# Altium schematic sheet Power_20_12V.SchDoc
size A4
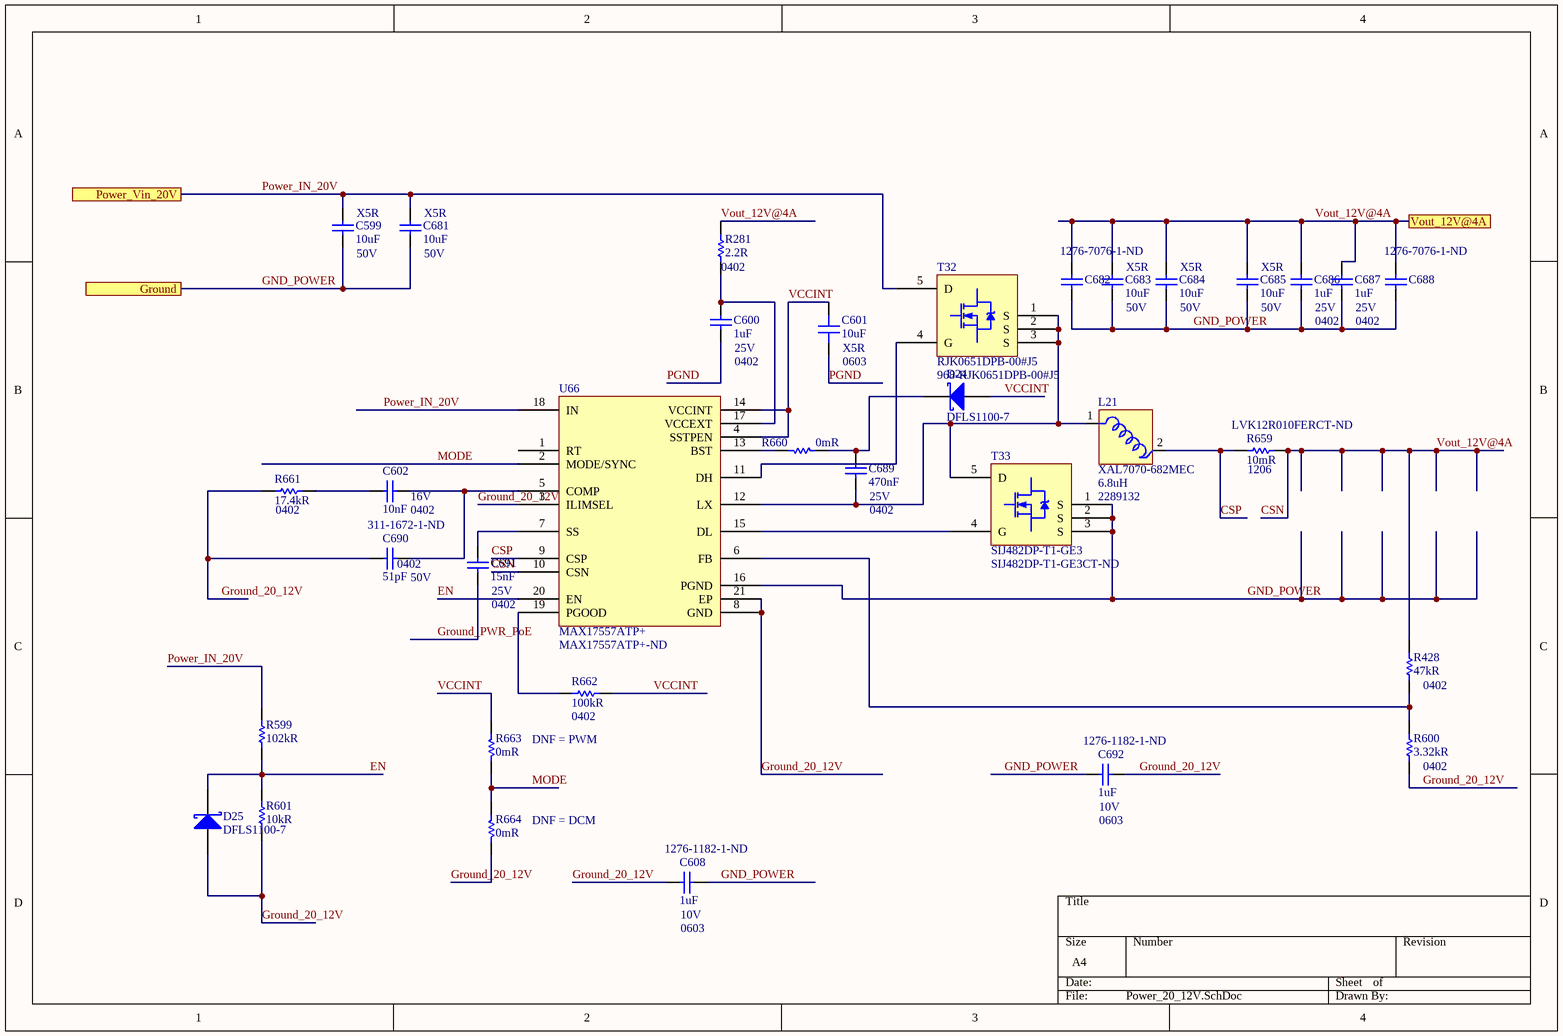
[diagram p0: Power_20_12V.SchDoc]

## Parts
C599  10uF  Voltage Rating (DC): 50V  Dielectric: X5R  [CAP 0805/2012 RF]
C600  1uF  Case/Package: 0402  Voltage Rating: 25V  [CAP 0402/1005 RF]
C601  10uF  Case/Package: 0603  Dielectric: X5R  [CAP 0603/1608 RF]
C602  10nF  Case/Package: 0402  Voltage Rating: 16V  [CAP 0402/1005 RF]
C608  1uF  Supplier Part Number 1: 1276-1182-1-ND  Case/Package: 0603  Voltage Rating: 10V  [CAP 0603/1608 RF]
C681  10uF  Voltage Rating (DC): 50V  Dielectric: X5R  [CAP 0805/2012 RF]
C682  Supplier Part Number 1: 1276-7076-1-ND  [CAP 0603/1608 RF]  (hidden comment: 22uF)
C683  10uF  Voltage Rating (DC): 50V  Dielectric: X5R  [CAP 0805/2012 RF]
C684  10uF  Voltage Rating (DC): 50V  Dielectric: X5R  [CAP 0805/2012 RF]
C685  10uF  Voltage Rating (DC): 50V  Dielectric: X5R  [CAP 0805/2012 RF]
C686  1uF  Case/Package: 0402  Voltage Rating: 25V  [CAP 0402/1005 RF]
C687  1uF  Case/Package: 0402  Voltage Rating: 25V  [CAP 0402/1005 RF]
C688  Supplier Part Number 1: 1276-7076-1-ND  [CAP 0603/1608 RF]  (hidden comment: 22uF)
C689  470nF  Case/Package: 0402  Voltage Rating: 25V  [CAP 0402/1005 RF]
C690  51pF  Supplier Part Number 1: 311-1672-1-ND  Case/Package: 0402  Voltage Rating: 50V  [CAP 0402/1005 RF]
C691  15nF  Case/Package: 0402  Voltage Rating: 25V  [CAP 0402/1005 RF]
C692  1uF  Supplier Part Number 1: 1276-1182-1-ND  Case/Package: 0603  Voltage Rating: 10V  [CAP 0603/1608 RF]
D24  DFLS1100-7  [DFLS1100]
D25  DFLS1100-7  [DFLS1100]
L21  XAL7070-682MEC  Inductance: 6.8uH  Supplier Part Number 1: 2289132
R281  2.2R  Case Code (Imperial): 0402  [RES 0402/1005 RF]
R428  47kR  Case/Package: 0402  [RES 0402/1005 RF]
R599  102kR  [RES 1206/3216]
R600  3.32kR  Case/Package: 0402  [RES 0402/1005 RF]
R601  10kR  [RES 0402/1005 RF]
R659  10mR  Supplier Part Number 1: LVK12R010FERCT-ND  Case/Package: 1206  [RES 1206/3216]
R660  0mR  [RES 0402/1005 RF]
R661  17.4kR  Case/Package: 0402  [RES 0402/1005 RF]
R662  100kR  Case/Package: 0402  [RES 0402/1005 RF]
R663  0mR  [RES 0402/1005 RF]
R664  0mR  [RES 0402/1005 RF]
T32  RJK0651DPB-00#J5  Supplier Part Number 1: 968-RJK0651DPB-00#J5  [RJK0651DPB]
T33  SIJ482DP-T1-GE3  Supplier Part Number 1: SIJ482DP-T1-GE3CT-ND  [SiJ482DP]
U66  MAX17557ATP+  Supplier Part Number 1: MAX17557ATP+-ND  [MAX17557]

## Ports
Ground, Power_Vin_20V, Vout_12V@4A

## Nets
CSN: C682.2 C683.2 C684.2 C685.2 C686.2 C687.2 C688.2 R281.2 R428.2 R659.2 U66.10(CSN) ; port Vout_12V@4A  [also labelled Vout_12V@4A]
CSP: L21.2 R659.1 U66.9(CSP)
EN: D25.1(K) R599.1 R601.1 U66.20(EN)
GND_POWER: C599.1 C608.2 C681.1 C682.1 C683.1 C684.1 C685.1 C686.1 C687.1 C688.1 C692.1 T33.1(S) T33.2(S) T33.3(S) U66.16(PGND) ; port Ground
Ground_20_12V: C608.1 C690.2 C692.2 D25.2(A) R600.1 R601.2 R661.1 R664.2 U66.3(ILIMSEL) U66.8(GND) U66.21(EP)
Ground_PWR_PoE: C691.1
MODE: R663.2 R664.1 U66.2(MODE/SYNC)
PGND: C600.1 C601.1
Power_IN_20V: C599.2 C681.2 R599.2 T32.5(D) U66.18(IN) ; port Power_Vin_20V
VCCINT: C601.2 D24.2(A) R662.1 R663.1 U66.4(SSTPEN) U66.14(VCCINT)
NetC600_2: C600.2 R281.1 U66.17(VCCEXT)
NetC602_1: C602.1 R661.2
NetC602_2: C602.2 C690.1 U66.5(COMP)
NetC689_1: C689.1 L21.1 T32.1(S) T32.2(S) T32.3(S) T33.5(D) U66.12(LX)
NetC689_2: C689.2 D24.1(K) R660.1
NetC691_2: C691.2 U66.7(SS)
NetR428_1: R428.1 R600.2 U66.6(FB)
NetR660_2: R660.2 U66.13(BST)
NetR662_2: R662.2 U66.19(PGOOD)
NetT32_4: T32.4(G) U66.11(DH)
NetT33_4: T33.4(G) U66.15(DL)

Not connected (* = marked no-connect by the designer): U66 1(RT)

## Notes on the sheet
- DNF = PWM
- (near R664) DNF = DCM

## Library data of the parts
C599 C681 C683-C685 = Capacitor: Manufacturer: Murata; Manufacturer Part Number: GRM21BR61H106KE43L; Tolerance: 10%
C600 C686 C687 = Capacitor: MURATA - GRT155R61E105KE01D - SMD Multilayer Ceramic Capacitor, 1 µF, 25 V, 0402 [1005 Metric], ± 10%, X5R, GRT Series - SMD Multilayer Ceramic Capacitor, 1 µF, 25 V, 0402 [1005 Metric], ± 10%, X5R, GRT Series
C601 = Capacitor: Manufacturer: Murata; Manufacturer Part Number: GRM188R61A106KE69D; Tolerance: 10%; Voltage Rating: 10V
C602 = Capacitor: CAP CER 10000PF 16V X7R 0402; Manufacturer: Yageo; Manufacturer Part Number: CC0402KRX7R7BB103; Tolerance: 10%; Insulation Resistance: 10GR; Dissipation Factor: 3.5%
C608 C692 = Capacitor: Cap Ceramic 1uF 10V X5R 10% SMD 0603 85C Paper T/R; Manufacturer: Samsung; Manufacturer Part Number: CL10A105KP8NNNC
C682 C688 = Capacitor: CAP CER 22UF 16V X5R 0603; Manufacturer: Samsung; Manufacturer Part Number: CL10A226MO7JZNC
C689 = Capacitor: CAP CER 0.47UF 25V X5R 0402; Manufacturer: Murata; Manufacturer Part Number: GRT155R61E474KE01D; Tolerance: 10%
C690 = Capacitor: Cap Ceramic 51pF 50V C0G 5% SMD 0402 125C Paper T/R; Manufacturer: Yageo; Manufacturer Part Number: CC0402JRNPO9BN510
C691 = Capacitor: Cap Ceramic 0.015uF 25V X7R 10% SMD 0402 125C Paper T/R; Manufacturer: Yageo; Manufacturer Part Number: CC0402KRX7R8BB153
D24 D25 = DFLS1100-7: DIODE SCHOTTKY 100V POWERDI123; Manufacturer: Diodes; Forward Voltage: 770mV; Forward Current: 1A; Peak Reverse Current: 1uA; Peak Non-Repetitive Surge Current: 50A; Max Forward Surge Current (Ifsm): 40A; Element Configuration: Single; Polarity: Standard; Capacitance: 36pF
L21 = XAL7070-682MEC: Power inductor, shielded, 20% tol, SMT, RoHS, halogen f; Manufacturer: Coilcraft; Core Material: Composite; Max DC Current: 9.2A; Self Resonant Frequency: 20MHz; DC Resistance (DCR): 19.62mR; Test Frequency: 100kHz; Saturation Current: 12.8A
R281 = Resistor: RES SMD 2.2 OHM 5% 1/16W 0402; Manufacturer: Yageo; Manufacturer Part Number: RC0402JR-072R2L; Power Rating: 62.5mW; Voltage Rating: 50V; Temperature Coefficient: 200ppm/°C; Max Power Dissipation: 63mW
R428 = Resistor: RES SMD 47K OHM 0.1% 1/16W 0402; Manufacturer: Panasonic; Manufacturer Part Number: ERA-2AEB473X; Power Rating: 63mW; Voltage Rating: 25V; Temperature Coefficient: 25ppm/°C
R599 = Resistor: RES 102K OHM 1% 1/16W 0402; Manufacturer: Stackpole Electronics; Manufacturer Part Number: RMCF0402FT102K; Power Rating: 62.5mW; Max Power Dissipation: 63mW; Temperature Coefficient: 100ppm/°C
R600 = Resistor: RES 3.32K OHM 1% 1/16W 0402; Manufacturer: Stackpole Electronics; Manufacturer Part Number: RMCF0402FT3K32; Max Power Dissipation: 63mW; Temperature Coefficient: 100ppm/°C
R601 = Resistor: Manufacturer 1: Yageo; Manufacturer Part Number 1: RC0402FR-0710KL; Tolerance: 1%; Temperature Coefficient: 100ppm/°C; Voltage Rating: 50V; Power Rating: 62.5mW
R659 = Resistor: RES 0.01 OHM 1% 1/2W 1206; Manufacturer: Ohmite; Manufacturer Part Number: LVK12R010FER; Power Rating: 500mW; Temperature Coefficient: 50ppm/°C
R660 R663 R664 = Resistor: Manufacturer 1: Yageo; Manufacturer Part Number 1: RC0402JR-070RL; Power Rating: 62.5mW; Tolerance: 5%; Voltage Rating: 50V; Max Power Dissipation: 63mW; Temperature Coefficient: 200ppm/°C
R661 = Resistor: RES SMD 17.4K OHM 1% 1/16W 0402; Manufacturer: Yageo; Manufacturer Part Number: RC0402FR-0717K4L; Power Rating: 62.5mW; Voltage Rating: 50V; Max Power Dissipation: 63mW; Temperature Coefficient: 100ppm/°C
R662 = Resistor: Manufacturer 1: Panasonic; Manufacturer Part Number 1: ERA-2AED104X; Tolerance: 0.5%; Power Rating: 63mW; Voltage Rating: 25V; Temperature Coefficient: 25ppm/°C
T32 = RJK0651DPB-00#J5: MOSFET N-CH 60V 25A LFPAK; Manufacturer: Renesas; Rise Time: 4.4ns; Turn-On Delay Time: 8.4ns; Turn-Off Delay Time: 42ns; Fall Time: 6.8ns; Gate to Source Voltage (Vgs): 20V; Rds On Max: 14mR; Input Capacitance: 2.03nF; Max Power Dissipation: 45W; Number of Elements: 1
T33 = SIJ482DP-T1-GE3: MOSFET 80V 6.2mOhm@10V 60A N-Ch MV T-FET; Manufacturer: Vishay; Rds On Max: 6.2mR; Input Capacitance: 2.425nF; Gate to Source Voltage (Vgs): 20V; Power Dissipation: 69.4W; Turn-Off Delay Time: 72ns; Number of Elements: 1; Element Configuration: Single; On-State Resistance: 9.5MR; Turn-On Delay Time: 28ns; Threshold Voltage: 1.5V
U66 = MAX17557ATP+: IC REG CTRLR BUCK 20-TQFN; Manufacturer: Maxim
